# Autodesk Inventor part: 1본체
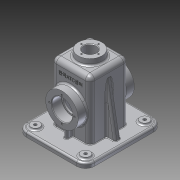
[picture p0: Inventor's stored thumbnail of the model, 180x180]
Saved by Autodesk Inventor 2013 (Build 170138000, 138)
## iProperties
Created: 2016-01
Part Number: 1본체
Material: 알루미늄 6061
Document SubType Name: Modeling
Designer: Administrator
Density: 2.71 g/cm^3
Mass: 808.98 g
Surface Area: 905.981 cm^2
Volume: 298.517 cm^3
Author: Administrator
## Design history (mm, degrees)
sketch "스케치1"
  geometry: L1 (-32.5, 32.5)-(32.5, 32.5); L2 (32.5, 32.5)-(32.5, -32.5); L3 (32.5, -32.5)-(-32.5, -32.5); L4 (-32.5, -32.5)-(-32.5, 32.5); 3 further points
  constraints: 8 end point, 2 midpoint, 2 parallel, 1 horizontal, 1 horizontal alignment, 1 perpendicular, 1 vertical alignment
  dimensions: "d0" = 65 distance of L2.end L3.end; "d1" = 65 distance of L1.end L2.end
extrude "돌출1" new body sketch "스케치1" distance "d2" = 110; taper "d3" = 0 deg
fillet "모깎기1" dims "d4" = 8
fillet "모깎기2" dims "d5" = 8
feature "쉘1" dims "d6" = 5
node "작업 평면1"
sketch "스케치2"
  geometry: C1 r 20 at (0, 0); 1 further point
  constraints: 1 centre point, 1 coincident
  dimensions: "d8" = 40 diameter of C1
extrude "돌출2" join sketch "스케치2" stored distance "d9" = 110; taper "d10" = 5 deg
sketch "스케치3"
  geometry: C1 r 20 at (0, 0) reference; C2 r 10.5 at (0, 0)
  constraints: 1 centre point, 1 coincident
  dimensions: "d11" = 21 diameter of C2
extrude "돌출3" cut sketch "스케치3" stored distance "d12" = 110; taper "d13" = 0 deg
chamfer "모따기1" distance "d14" = 1; stored, may be unused: second distance "d15" = 2, angle "d16" = 45 deg
sketch "스케치4" dims "d17" = 29
  geometry: L1 (0, 0)-(0, -14.5); C1 r 11.5 at (0, 0) reference; 1 further point
  constraints: 2 coincident, 2 end point, 1 vertical, 1 vertical alignment, 2 other
hole "구멍1" sketch "스케치4" at (0, -14.5) diameter "d18" = 2.459; stored, may be unused: countersink angle "d22" = 90 deg, drill point angle "d24" = 118 deg; dims "d19" = 7, "d20" = 4, "d21" = 2, "d23" = 9
sketch "스케치5"
  geometry: L1 (49, 0)-(0, 0) reference; C1 r 27.5 at (24.5, 55); 2 further points
  constraints: 1 centre point, 1 midpoint, 1 vertical alignment
  dimensions: "d28" = 55 diameter of C1; "d29" = 55 distance of point (24.5, 0) C1.centre
extrude "돌출4" join sketch "스케치5" distance "d30" = 15; taper "d32" = 0 deg; dims "d31" = 3, "d33" = 0
sketch "스케치6"
  geometry: C1 r 27.5 at (0, 0) reference; 2 further points
  constraints: 1 coincident
hole "구멍2" sketch "스케치6" at (0, 0) diameter "d35" = 35; stored, may be unused: countersink angle "d39" = 90 deg, drill point angle "d41" = 0 deg; dims "d36" = 7, "d37" = 4, "d38" = 2, "d40" = 17
sketch "스케치7"
  geometry: C1 r 17.5 at (0, 0) reference; 2 further points
  constraints: 1 coincident
hole "구멍3" sketch "스케치7" at (0, 0) diameter "d42" = 30; stored, may be unused: countersink angle "d46" = 90 deg, drill point angle "d48" = 0 deg; dims "d43" = 7, "d44" = 4, "d45" = 2, "d47" = 17
fillet "모깎기4" dims "d49" = 3
fillet "모깎기5" dims "d50" = 0.3
sketch "스케치9" dims "d51" = 42
  geometry: L1 (0, 0)-(0, -21); C1 r 27.5 at (0, 0) reference; 2 further points
  constraints: 2 coincident, 2 end point, 1 vertical, 1 vertical alignment, 2 other
hole "구멍4" sketch "스케치9" at (0, -21) diameter "d52" = 3.242; stored, may be unused: countersink angle "d56" = 90 deg, drill point angle "d58" = 118 deg; dims "d53" = 8, "d54" = 4, "d55" = 2, "d57" = 10
sketch "스케치10"
  geometry: L1 (24.5, 32.5)-(-24.5, 32.5) reference; L2 (-32.5, 24.5)-(-32.5, -24.5) reference; L3 (-24.5, -32.5)-(24.5, -32.5) reference; L4 (32.5, -24.5)-(32.5, 24.5) reference; L5 (-52.5, -60)-(52.5, -60); L6 (52.5, -60)-(52.5, 60); L7 (52.5, 60)-(-52.5, 60); L8 (-52.5, 60)-(-52.5, -60); A1 r 8 centre (24.5, 24.5) between (32.5, 24.5) and (24.5, 32.5) reference; A2 r 8 centre (-24.5, 24.5) between (-24.5, 32.5) and (-32.5, 24.5) reference; A3 r 8 centre (-24.5, -24.5) between (-32.5, -24.5) and (-24.5, -32.5) reference; A4 r 8 centre (24.5, -24.5) between (24.5, -32.5) and (32.5, -24.5) reference; 3 further points
  constraints: 8 end point, 2 midpoint, 2 parallel, 1 horizontal, 1 horizontal alignment, 1 perpendicular, 1 vertical alignment
  dimensions: "d62" = 105 distance of L7.end L6.end; "d63" = 120 distance of L6.end L5.end
extrude "돌출5" join sketch "스케치10" distance "d64" = 2; taper "d65" = 0 deg
fillet "모깎기6" dims "d66" = 10
sketch "스케치11"
  geometry: L1 (24.5, 32.5)-(-24.5, 32.5) reference; L2 (32.5, -24.5)-(32.5, 24.5) reference; L3 (-24.5, -32.5)-(24.5, -32.5) reference; L4 (-32.5, 24.5)-(-32.5, -24.5) reference; L5 (57.5, -65)-(-57.5, -65); L6 (-57.5, -65)-(-57.5, 65); L7 (-57.5, 65)-(57.5, 65); L8 (57.5, 65)-(57.5, -65); A1 r 8 centre (24.5, 24.5) between (32.5, 24.5) and (24.5, 32.5) reference; A2 r 8 centre (24.5, -24.5) between (24.5, -32.5) and (32.5, -24.5) reference; A3 r 8 centre (-24.5, -24.5) between (-32.5, -24.5) and (-24.5, -32.5) reference; A4 r 8 centre (-24.5, 24.5) between (-24.5, 32.5) and (-32.5, 24.5) reference; 3 further points
  constraints: 8 end point, 2 midpoint, 2 parallel, 1 horizontal, 1 horizontal alignment, 1 perpendicular, 1 vertical alignment
  dimensions: "d67" = 115 distance of L6.end L7.end; "d68" = 130 distance of L5.end L6.end
extrude "돌출6" join sketch "스케치11" distance "d69" = 8; taper "d70" = 0 deg
fillet "모깎기7" dims "d71" = 15
sketch "스케치12"
  geometry: L1 (42.5, 50)-(-42.5, 50); L2 (-42.5, 50)-(-42.5, -50); L3 (-42.5, -50)-(42.5, -50); L4 (42.5, -50)-(42.5, 50); C1 r 7.5 at (-42.5, 50); C2 r 7.5 at (42.5, 50); C3 r 7.5 at (42.5, -50); C4 r 7.5 at (-42.5, -50); 3 further points
  constraints: 8 end point, 4 centre point, 3 coincident, 2 midpoint, 2 parallel, 1 horizontal, 1 horizontal alignment, 1 perpendicular, 1 vertical alignment
  dimensions: "d72" = 85 distance of L3.end L2.end; "d73" = 100 distance of L2.end L1.end; "d74" = 15 diameter of C1; "d75" = 15 diameter of C2; "d76" = 15 diameter of C3; "d77" = 15 diameter of C4
extrude "돌출7" join sketch "스케치12" distance "d78" = 3; taper "d79" = 0 deg
hole "구멍5" diameter "d82" = 5; stored, may be unused: countersink angle "d86" = 90 deg, drill point angle "d88" = 0 deg; dims "d80" = 10, "d81" = 10, "d83" = 8, "d84" = 4, "d85" = 2, "d87" = 10
hole "구멍6" diameter "d91" = 5; stored, may be unused: countersink angle "d95" = 90 deg, drill point angle "d97" = 0 deg; dims "d89" = 10, "d90" = 10, "d92" = 8, "d93" = 4, "d94" = 2, "d96" = 10
hole "구멍7" diameter "d100" = 5; stored, may be unused: countersink angle "d104" = 90 deg, drill point angle "d106" = 0 deg; dims "d98" = 10, "d99" = 10, "d101" = 8, "d102" = 4, "d103" = 2, "d105" = 10
hole "구멍8" diameter "d109" = 5; stored, may be unused: countersink angle "d113" = 90 deg, drill point angle "d115" = 0 deg; dims "d107" = 10, "d108" = 10, "d110" = 8, "d111" = 4, "d112" = 2, "d114" = 10
fillet "모깎기8" dims "d116" = 3
fillet "모깎기9" dims "d117" = 3
node "작업 평면3"
sketch "스케치13"
  geometry: L1 (35, 17)-(36, 18) reference; L2 (36, 18)-(37.771, 18) reference; L3 (37.771, 18)-(37.771, 9) reference; L4 (37.771, 9)-(39, 8.261) reference; L5 (39, 8.261)-(40.23, 9) reference; L6 (40.23, 9)-(40.23, 18) reference; L7 (40.23, 18)-(44.5, 18) reference; L8 (44.5, 18)-(45.375, 8) reference; L9 (45.375, 8)-(49, 8) reference; L10 (57, 0)-(57, -92) reference; L11 (57, -92)-(79, -92) reference; L12 (82, -95)-(82, -100) reference; L13 (82, -100)-(77, -100) reference; L14 (77, -100)-(77, -102) reference; L15 (77, -102)-(52, -102) reference; L16 (52, -102)-(52, 0) reference; L17 (49, 3)-(35, 3) reference; L18 (35, 3)-(35, 17) reference; L19 (0, 8)-(3.625, 8) reference; L20 (3.625, 8)-(4.5, 18) reference; L21 (4.5, 18)-(8.771, 18) reference; L22 (8.771, 18)-(8.771, 9) reference; L23 (8.771, 9)-(10, 8.261) reference; L24 (10, 8.261)-(11.23, 9) reference; L25 (11.23, 9)-(11.23, 18) reference; L26 (11.23, 18)-(13, 18) reference; L27 (13, 18)-(14, 17) reference; L28 (14, 17)-(14, 3) reference; L29 (14, 3)-(0, 3) reference; L30 (-3, 0)-(-3, -102) reference; L31 (-3, -102)-(-28, -102) reference; L32 (-28, -102)-(-28, -100) reference; L33 (-28, -100)-(-33, -100) reference; L34 (-33, -100)-(-33, -95) reference; L35 (-30, -92)-(-8, -92) reference; L36 (-8, -92)-(-8, 0) reference; L37 (-8, -6.931)-(-23, -92); A1 r 8 centre (49, 0) between (57, 0) and (49, 8) reference; A2 r 3 centre (79, -95) between (82, -95) and (79, -92) reference; A3 r 3 centre (49, 0) between (52, 0) and (49, 3) reference; A4 r 8 centre (0, 0) between (0, 8) and (-8, 0) reference; A5 r 3 centre (0, 0) between (0, 3) and (-3, 0) reference; A6 r 3 centre (-30, -95) between (-30, -92) and (-33, -95) reference; 1 further point
  constraints: 2 end point, 2 point on line
  dimensions: "d118" = 10 horizontal distance of L37.end L34.end; "d119" = 10 deg angle of L34 L37
feature "리브1" sketch "스케치13" dims "d120" = 1, "d121" = 10, "d122" = 0, "d123" = 0, "d124" = 1, "d125" = 1
node "작업 평면4"
sketch "스케치14"
  geometry: L1 (64.5, 55.3)-(64.5, 72) reference; L2 (64.5, 72)-(66.379, 72) reference; L3 (66.379, 72)-(66.379, 62) reference; L4 (66.379, 62)-(68, 61.026) reference; L5 (68, 61.026)-(69.621, 62) reference; L6 (69.621, 62)-(69.621, 72) reference; L7 (69.621, 72)-(74.5, 72) reference; L8 (74.5, 72)-(74.5, 60) reference; L9 (77.5, 57)-(92, 57) reference; L10 (92, 57)-(92, 86.5) reference; L11 (95, 89.5)-(100, 89.5) reference; L12 (100, 89.5)-(100, 84.5) reference; L13 (100, 84.5)-(102, 84.5) reference; L14 (102, 84.5)-(102, 52) reference; L15 (102, 52)-(62, 52) reference; L16 (62, 52)-(62, 55) reference; L17 (62, 55)-(64.2, 55) reference; L18 (64.2, -6)-(62, -6) reference; L19 (62, -6)-(62, -3) reference; L20 (62, -3)-(102, -3) reference; L21 (102, -3)-(102, -35.5) reference; L22 (102, -35.5)-(100, -35.5) reference; L23 (100, -35.5)-(100, -40.5) reference; L24 (100, -40.5)-(95, -40.5) reference; L25 (92, -37.5)-(92, -8) reference; L26 (92, -8)-(77.5, -8) reference; L27 (74.5, -11)-(74.5, -23) reference; L28 (74.5, -23)-(69.621, -23) reference; L29 (69.621, -23)-(69.621, -13) reference; L30 (69.621, -13)-(68, -12.026) reference; L31 (68, -12.026)-(66.379, -13) reference; L32 (66.379, -13)-(66.379, -23) reference; L33 (66.379, -23)-(64.5, -23) reference; L34 (64.5, -23)-(64.5, -6.3) reference; L35 (-9, 37.771)-(-8.261, 39) reference; L36 (-8.261, 39)-(-9, 40.23) reference; L37 (-9, 40.23)-(-18, 40.23) reference; L38 (-18, 40.23)-(-18, 44.5) reference; L39 (-18, 44.5)-(-8, 45.375) reference; L40 (-8, 45.375)-(-8, 49) reference; L41 (0, 57)-(16.5, 57) reference; L42 (19.5, 60)-(19.5, 72) reference; L43 (19.5, 72)-(24.379, 72) reference; L44 (24.379, 72)-(24.379, 62) reference; L45 (24.379, 62)-(26, 61.026) reference; L46 (26, 61.026)-(27.621, 62) reference; L47 (27.621, 62)-(27.621, 72) reference; L48 (27.621, 72)-(29.5, 72) reference; L49 (29.5, 72)-(29.5, 55.3) reference; L50 (29.8, 55)-(32, 55) reference; L51 (32, 55)-(32, 52) reference; L52 (32, 52)-(0, 52) reference; L53 (-3, 49)-(-3, 35) reference; L54 (-3, 35)-(-17, 35) reference; L55 (-17, 35)-(-18, 36) reference; L56 (-18, 36)-(-18, 37.771) reference; L57 (-18, 37.771)-(-9, 37.771) reference; L58 (-8.261, 10)-(-9, 11.229) reference; L59 (-9, 11.229)-(-18, 11.229) reference; L60 (-18, 11.229)-(-18, 13) reference; L61 (-18, 13)-(-17, 14) reference; L62 (-17, 14)-(-3, 14) reference; L63 (-3, 14)-(-3, 0) reference; L64 (0, -3)-(32, -3) reference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; A1 r 0.3 centre (64.2, 55.3) between (64.2, 55) and (64.5, 55.3) reference; A2 r 3 centre (77.5, 60) between (74.5, 60) and (77.5, 57) reference; A3 r 3 centre (95, 86.5) between (95, 89.5) and (92, 86.5) reference; A4 r 0.3 centre (64.2, -6.3) between (64.5, -6.3) and (64.2, -6) reference; A5 r 3 centre (95, -37.5) between (92, -37.5) and (95, -40.5) reference; A6 r 3 centre (77.5, -11) between (77.5, -8) and (74.5, -11) reference; A7 r 8 centre (0, 49) between (0, 57) and (-8, 49) reference; A8 r 3 centre (16.5, 60) between (16.5, 57) and (19.5, 60) reference; A9 r 0.3 centre (29.8, 55.3) between (29.5, 55.3) and (29.8, 55) reference; A10 r 3 centre (0, 49) between (0, 52) and (-3, 49) reference; A11 r 3 centre (0, 0) between (-3, 0) and (0, -3) reference; A12 r 0.3 centre (29.8, -6.3) between (29.8, -6) and (29.5, -6.3) reference; A13 r 3 centre (16.5, -11) between (19.5, -11) and (16.5, -8) reference; A14 r 8 centre (0, 0) between (-8, 0) and (0, -8) reference; 1 further point
  constraints: 2 end point, 2 point on line, 1 horizontal
  dimensions: "d126" = 15 distance between parallel lines of L20 L82
feature "리브2" sketch "스케치14" dims "d127" = 1, "d128" = 6, "d129" = 0, "d130" = 0, "d131" = 1, "d132" = 1
fillet "모깎기10" dims "d133" = 3
fillet "모깎기11" dims "d134" = 3
chamfer "모따기2" distance "d136" = 1; stored, may be unused: second distance "d137" = 2, angle "d138" = 45 deg
sketch "스케치15"
  geometry: L1 (4.5, 18)-(44.5, 18) reference; L2 (-8, 0)-(-8, -92) reference; A1 r 30.5 centre (24.5, -47) between (49, -28.834) and (0, -28.834) reference; 3 further points
  constraints: 1 vertical alignment, 1 other
  dimensions: "d139" = 27 distance from line of L1 point (24.5, -9); "d140" = 32.5 distance from line of point (24.5, -9) L2 (derived)
feature "엠보싱1" sketch "스케치15" dims "d6" = 5, "d141" = 0.5, "d142" = 0
fillet "모깎기13" dims "d143" = 3
fillet "모깎기14" dims "d144" = 1
node "솔리드1"
pattern_circular "원형 패턴1" dims angle "d26" = 360 deg
mirror "대칭1"
pattern_circular "원형 패턴2" dims angle "d60" = 360 deg
mirror "대칭2"
mirror "대칭3"
mirror "대칭4"
node "절단 모서리 투영2"
node "절단 모서리 투영3"
